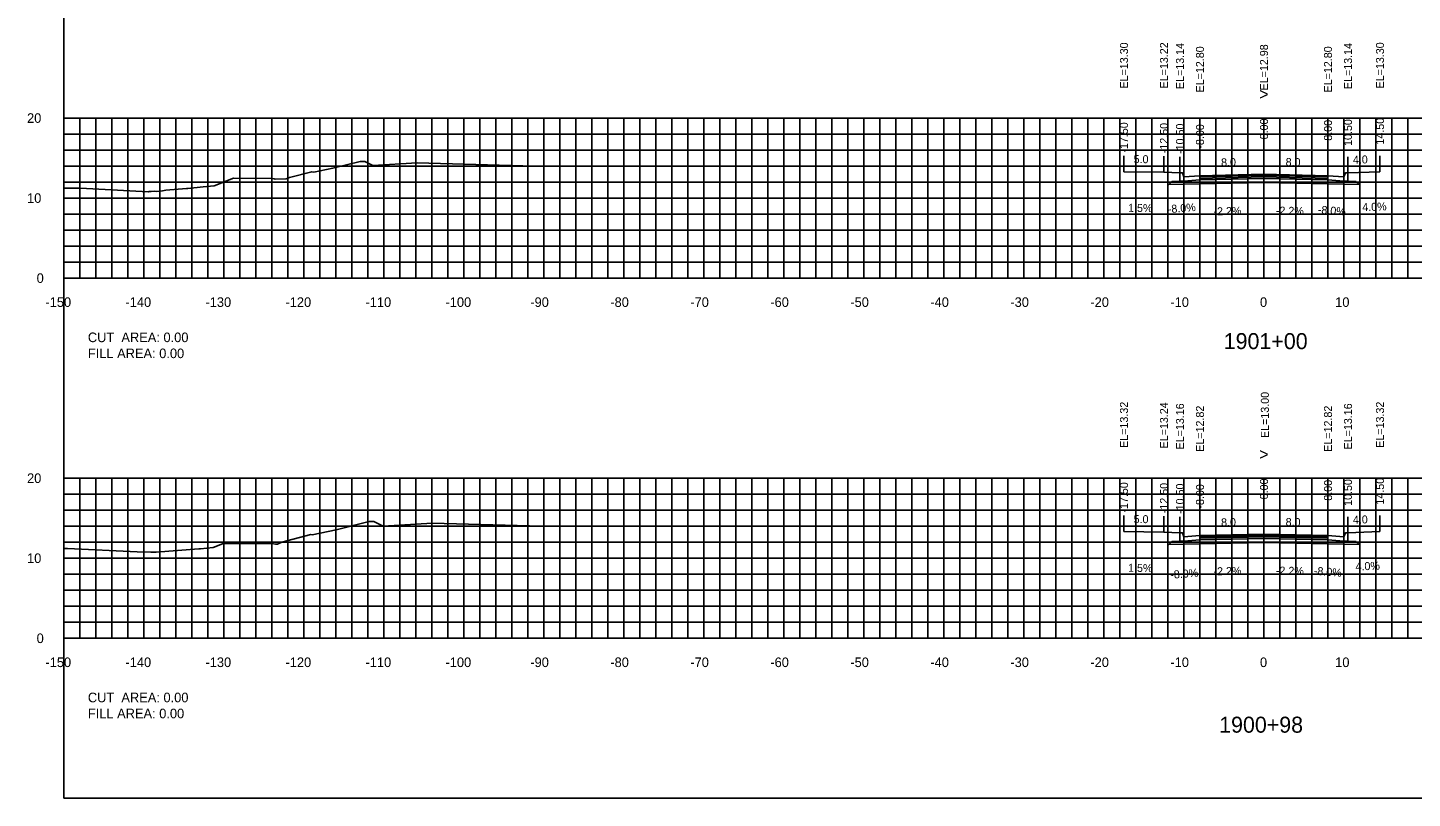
# Model space of a CAD drawing. Extents: x 1800768 to 1802445, y 250079 to 250269.
# Drawn here: x 1802136.5 to 1802309.5, y 250079.4 to 250175.7 of the extents above; entities that cross this region are included whole.
import ezdxf

# ---------------------------------------------------------------- set-up
doc = ezdxf.new("R2010")
doc.units = 0
for name, color, linetype in [('1', 7, 'Continuous'), ('10', 7, 'Continuous'), ('3', 7, 'Continuous'), ('31', 7, 'Continuous'), ('4', 7, 'Continuous'), ('60', 7, 'Continuous'), ('ANNO-TXT', 7, 'Continuous'), ('BASE', 7, 'Continuous'), ('CL-CNST', 7, 'Continuous'), ('Level 62', 7, 'Continuous'), ('LOWER BINDER', 7, 'Continuous'), ('M-ROADS', 7, 'Continuous'), ('UPPER BINDER', 7, 'Continuous'), ('WEARING', 7, 'Continuous')]:
    doc.layers.add(name, color=color, linetype=linetype)

msp = doc.modelspace()

# ---------------------------------------------------------------- linework, layer by layer
for p, q in [((1802273.5, 250157.73), (1802273.5, 250159.73)), ((1802278.5, 250157.66), (1802278.5, 250159.66)), ((1802280.5, 250157.57), (1802280.5, 250159.57)), ((1802291, 250157.41), (1802291, 250159.41)), ((1802301.5, 250157.57), (1802301.5, 250159.57)), ((1802305.5, 250157.73), (1802305.5, 250159.73)), ((1802283, 250157.23), (1802283, 250159.23)), ((1802299, 250157.23), (1802299, 250159.23)), ((1802273.5, 250112.75), (1802273.5, 250114.75)), ((1802278.5, 250112.68), (1802278.5, 250114.68)), ((1802280.5, 250112.6), (1802280.5, 250114.6)), ((1802291, 250112.43), (1802291, 250114.43)), ((1802301.5, 250112.6), (1802301.5, 250114.6)), ((1802305.5, 250112.76), (1802305.5, 250114.76)), ((1802283, 250112.26), (1802283, 250114.26)), ((1802299, 250112.26), (1802299, 250114.26))]:
    msp.add_line(p, q)
for points in [[(1802141, 250079.43), (1802441, 250079.43), (1802441, 250269.43), (1802141, 250269.43)], [(1802283, 250157.23), (1802281, 250157.07), (1802280.83, 250157.57), (1802280.5, 250157.57), (1802280.5, 250156.54), (1802281, 250156.54), (1802283, 250156.7)], [(1802299, 250157.23), (1802301, 250157.07), (1802301.17, 250157.57), (1802301.5, 250157.57), (1802301.5, 250156.54), (1802301, 250156.54), (1802299, 250156.7)], [(1802283, 250112.26), (1802281, 250112.1), (1802280.83, 250112.6), (1802280.5, 250112.6), (1802280.5, 250111.57), (1802281, 250111.57), (1802283, 250111.73)], [(1802299, 250112.26), (1802301, 250112.1), (1802301.17, 250112.6), (1802301.5, 250112.6), (1802301.5, 250111.57), (1802301, 250111.57), (1802299, 250111.73)]]:
    msp.add_lwpolyline(points, close=True)
at = {"layer": '60'}
for p, q in [((1802140.94, 250164.43), (1802141, 250164.43)), ((1802141, 250144.43), (1802141, 250164.43)), ((1802140.94, 250154.43), (1802141, 250154.43)), ((1802140.94, 250144.43), (1802141, 250144.43)), ((1802141, 250144.43), (1802441, 250144.43)), ((1802141, 250144.37), (1802141, 250144.43)), ((1802151, 250144.37), (1802151, 250144.43)), ((1802161, 250144.37), (1802161, 250144.43)), ((1802171, 250144.37), (1802171, 250144.43)), ((1802181, 250144.37), (1802181, 250144.43)), ((1802191, 250144.37), (1802191, 250144.43)), ((1802201, 250144.37), (1802201, 250144.43)), ((1802211, 250144.37), (1802211, 250144.43)), ((1802221, 250144.37), (1802221, 250144.43)), ((1802231, 250144.37), (1802231, 250144.43)), ((1802241, 250144.37), (1802241, 250144.43)), ((1802251, 250144.37), (1802251, 250144.43)), ((1802261, 250144.37), (1802261, 250144.43)), ((1802271, 250144.37), (1802271, 250144.43)), ((1802281, 250144.37), (1802281, 250144.43)), ((1802291, 250144.37), (1802291, 250144.43)), ((1802301, 250144.37), (1802301, 250144.43)), ((1802140.94, 250119.43), (1802141, 250119.43)), ((1802141, 250099.43), (1802141, 250119.43)), ((1802140.94, 250109.43), (1802141, 250109.43)), ((1802140.94, 250099.43), (1802141, 250099.43)), ((1802141, 250099.43), (1802441, 250099.43)), ((1802141, 250099.37), (1802141, 250099.43)), ((1802151, 250099.37), (1802151, 250099.43)), ((1802161, 250099.37), (1802161, 250099.43)), ((1802171, 250099.37), (1802171, 250099.43)), ((1802181, 250099.37), (1802181, 250099.43)), ((1802191, 250099.37), (1802191, 250099.43)), ((1802201, 250099.37), (1802201, 250099.43)), ((1802211, 250099.37), (1802211, 250099.43)), ((1802221, 250099.37), (1802221, 250099.43)), ((1802231, 250099.37), (1802231, 250099.43)), ((1802241, 250099.37), (1802241, 250099.43)), ((1802251, 250099.37), (1802251, 250099.43)), ((1802261, 250099.37), (1802261, 250099.43)), ((1802271, 250099.37), (1802271, 250099.43)), ((1802281, 250099.37), (1802281, 250099.43)), ((1802291, 250099.37), (1802291, 250099.43)), ((1802301, 250099.37), (1802301, 250099.43))]:
    msp.add_line(p, q, dxfattribs=at)
at = {"layer": 'BASE'}
for points in [[(1802299, 250156.2), (1802302.9, 250156.12), (1802302.5, 250156.52), (1802301.5, 250156.54), (1802301, 250156.54), (1802299, 250156.7), (1802291, 250156.88), (1802283, 250156.7), (1802281, 250156.54), (1802280.5, 250156.54), (1802279.5, 250156.52), (1802279.1, 250156.12), (1802283, 250156.2), (1802291, 250156.38)], [(1802299, 250111.23), (1802302.9, 250111.14), (1802302.5, 250111.54), (1802301.5, 250111.57), (1802301, 250111.57), (1802299, 250111.73), (1802291, 250111.9), (1802283, 250111.73), (1802281, 250111.57), (1802280.5, 250111.57), (1802279.5, 250111.54), (1802279.1, 250111.14), (1802283, 250111.23), (1802291, 250111.4)]]:
    msp.add_lwpolyline(points, close=True, dxfattribs=at)
at = {"layer": 'CL-CNST'}
for points in [[(1802273.5, 250157.73), (1802278.5, 250157.66), (1802280.5, 250157.57), (1802280.83, 250157.57), (1802281, 250157.07), (1802283, 250157.23), (1802291, 250157.41), (1802299, 250157.23), (1802301, 250157.07), (1802301.17, 250157.57), (1802301.5, 250157.57), (1802305.5, 250157.73)], [(1802273.5, 250112.75), (1802278.5, 250112.68), (1802280.5, 250112.6), (1802280.83, 250112.6), (1802281, 250112.1), (1802283, 250112.26), (1802291, 250112.43), (1802299, 250112.26), (1802301, 250112.1), (1802301.17, 250112.6), (1802301.5, 250112.6), (1802305.5, 250112.76)]]:
    msp.add_lwpolyline(points, dxfattribs=at)
at = {"layer": 'Level 62'}
for p, q in [((1802141, 250164.43), (1802441, 250164.43)), ((1802141, 250144.43), (1802141, 250164.43)), ((1802143, 250144.43), (1802143, 250164.43)), ((1802145, 250144.43), (1802145, 250164.43)), ((1802147, 250144.43), (1802147, 250164.43)), ((1802149, 250144.43), (1802149, 250164.43)), ((1802151, 250144.43), (1802151, 250164.43)), ((1802153, 250144.43), (1802153, 250164.43)), ((1802155, 250144.43), (1802155, 250164.43)), ((1802157, 250144.43), (1802157, 250164.43)), ((1802159, 250144.43), (1802159, 250164.43)), ((1802161, 250144.43), (1802161, 250164.43)), ((1802163, 250144.43), (1802163, 250164.43)), ((1802165, 250144.43), (1802165, 250164.43)), ((1802167, 250144.43), (1802167, 250164.43)), ((1802169, 250144.43), (1802169, 250164.43)), ((1802171, 250144.43), (1802171, 250164.43)), ((1802173, 250144.43), (1802173, 250164.43)), ((1802175, 250144.43), (1802175, 250164.43)), ((1802177, 250144.43), (1802177, 250164.43)), ((1802179, 250144.43), (1802179, 250164.43)), ((1802181, 250144.43), (1802181, 250164.43)), ((1802183, 250144.43), (1802183, 250164.43)), ((1802185, 250144.43), (1802185, 250164.43)), ((1802187, 250144.43), (1802187, 250164.43)), ((1802189, 250144.43), (1802189, 250164.43)), ((1802191, 250144.43), (1802191, 250164.43)), ((1802193, 250144.43), (1802193, 250164.43)), ((1802195, 250144.43), (1802195, 250164.43)), ((1802197, 250144.43), (1802197, 250164.43)), ((1802199, 250144.43), (1802199, 250164.43)), ((1802201, 250144.43), (1802201, 250164.43)), ((1802203, 250144.43), (1802203, 250164.43)), ((1802205, 250144.43), (1802205, 250164.43)), ((1802207, 250144.43), (1802207, 250164.43)), ((1802209, 250144.43), (1802209, 250164.43)), ((1802211, 250144.43), (1802211, 250164.43)), ((1802213, 250144.43), (1802213, 250164.43)), ((1802215, 250144.43), (1802215, 250164.43)), ((1802217, 250144.43), (1802217, 250164.43)), ((1802219, 250144.43), (1802219, 250164.43)), ((1802221, 250144.43), (1802221, 250164.43)), ((1802223, 250144.43), (1802223, 250164.43)), ((1802225, 250144.43), (1802225, 250164.43)), ((1802227, 250144.43), (1802227, 250164.43)), ((1802229, 250144.43), (1802229, 250164.43)), ((1802231, 250144.43), (1802231, 250164.43)), ((1802233, 250144.43), (1802233, 250164.43)), ((1802235, 250144.43), (1802235, 250164.43)), ((1802237, 250144.43), (1802237, 250164.43)), ((1802239, 250144.43), (1802239, 250164.43)), ((1802241, 250144.43), (1802241, 250164.43)), ((1802243, 250144.43), (1802243, 250164.43)), ((1802245, 250144.43), (1802245, 250164.43)), ((1802247, 250144.43), (1802247, 250164.43)), ((1802249, 250144.43), (1802249, 250164.43)), ((1802251, 250144.43), (1802251, 250164.43)), ((1802253, 250144.43), (1802253, 250164.43)), ((1802255, 250144.43), (1802255, 250164.43)), ((1802257, 250144.43), (1802257, 250164.43)), ((1802259, 250144.43), (1802259, 250164.43)), ((1802261, 250144.43), (1802261, 250164.43)), ((1802263, 250144.43), (1802263, 250164.43)), ((1802265, 250144.43), (1802265, 250164.43)), ((1802267, 250144.43), (1802267, 250164.43)), ((1802269, 250144.43), (1802269, 250164.43)), ((1802271, 250144.43), (1802271, 250164.43)), ((1802273, 250144.43), (1802273, 250164.43)), ((1802275, 250144.43), (1802275, 250164.43)), ((1802277, 250144.43), (1802277, 250164.43)), ((1802279, 250144.43), (1802279, 250164.43)), ((1802281, 250144.43), (1802281, 250164.43)), ((1802283, 250144.43), (1802283, 250164.43)), ((1802285, 250144.43), (1802285, 250164.43)), ((1802287, 250144.43), (1802287, 250164.43)), ((1802289, 250144.43), (1802289, 250164.43)), ((1802291, 250144.43), (1802291, 250164.43)), ((1802293, 250144.43), (1802293, 250164.43)), ((1802295, 250144.43), (1802295, 250164.43)), ((1802297, 250144.43), (1802297, 250164.43)), ((1802299, 250144.43), (1802299, 250164.43)), ((1802301, 250144.43), (1802301, 250164.43)), ((1802303, 250144.43), (1802303, 250164.43)), ((1802305, 250144.43), (1802305, 250164.43)), ((1802307, 250144.43), (1802307, 250164.43)), ((1802309, 250144.43), (1802309, 250164.43)), ((1802141, 250162.43), (1802441, 250162.43)), ((1802141, 250160.43), (1802441, 250160.43)), ((1802141, 250158.43), (1802441, 250158.43)), ((1802141, 250156.43), (1802441, 250156.43)), ((1802141, 250154.43), (1802441, 250154.43)), ((1802141, 250152.43), (1802441, 250152.43)), ((1802141, 250150.43), (1802441, 250150.43)), ((1802141, 250148.43), (1802441, 250148.43)), ((1802141, 250146.43), (1802441, 250146.43)), ((1802141, 250144.43), (1802441, 250144.43)), ((1802141, 250119.43), (1802441, 250119.43)), ((1802141, 250099.43), (1802141, 250119.43)), ((1802143, 250099.43), (1802143, 250119.43)), ((1802145, 250099.43), (1802145, 250119.43)), ((1802147, 250099.43), (1802147, 250119.43)), ((1802149, 250099.43), (1802149, 250119.43)), ((1802151, 250099.43), (1802151, 250119.43)), ((1802153, 250099.43), (1802153, 250119.43)), ((1802155, 250099.43), (1802155, 250119.43)), ((1802157, 250099.43), (1802157, 250119.43)), ((1802159, 250099.43), (1802159, 250119.43)), ((1802161, 250099.43), (1802161, 250119.43)), ((1802163, 250099.43), (1802163, 250119.43)), ((1802165, 250099.43), (1802165, 250119.43)), ((1802167, 250099.43), (1802167, 250119.43)), ((1802169, 250099.43), (1802169, 250119.43)), ((1802171, 250099.43), (1802171, 250119.43)), ((1802173, 250099.43), (1802173, 250119.43)), ((1802175, 250099.43), (1802175, 250119.43)), ((1802177, 250099.43), (1802177, 250119.43)), ((1802179, 250099.43), (1802179, 250119.43)), ((1802181, 250099.43), (1802181, 250119.43)), ((1802183, 250099.43), (1802183, 250119.43)), ((1802185, 250099.43), (1802185, 250119.43)), ((1802187, 250099.43), (1802187, 250119.43)), ((1802189, 250099.43), (1802189, 250119.43)), ((1802191, 250099.43), (1802191, 250119.43)), ((1802193, 250099.43), (1802193, 250119.43)), ((1802195, 250099.43), (1802195, 250119.43)), ((1802197, 250099.43), (1802197, 250119.43)), ((1802199, 250099.43), (1802199, 250119.43)), ((1802201, 250099.43), (1802201, 250119.43)), ((1802203, 250099.43), (1802203, 250119.43)), ((1802205, 250099.43), (1802205, 250119.43)), ((1802207, 250099.43), (1802207, 250119.43)), ((1802209, 250099.43), (1802209, 250119.43)), ((1802211, 250099.43), (1802211, 250119.43)), ((1802213, 250099.43), (1802213, 250119.43)), ((1802215, 250099.43), (1802215, 250119.43)), ((1802217, 250099.43), (1802217, 250119.43)), ((1802219, 250099.43), (1802219, 250119.43)), ((1802221, 250099.43), (1802221, 250119.43)), ((1802223, 250099.43), (1802223, 250119.43)), ((1802225, 250099.43), (1802225, 250119.43)), ((1802227, 250099.43), (1802227, 250119.43)), ((1802229, 250099.43), (1802229, 250119.43)), ((1802231, 250099.43), (1802231, 250119.43)), ((1802233, 250099.43), (1802233, 250119.43)), ((1802235, 250099.43), (1802235, 250119.43)), ((1802237, 250099.43), (1802237, 250119.43)), ((1802239, 250099.43), (1802239, 250119.43)), ((1802241, 250099.43), (1802241, 250119.43)), ((1802243, 250099.43), (1802243, 250119.43)), ((1802245, 250099.43), (1802245, 250119.43)), ((1802247, 250099.43), (1802247, 250119.43)), ((1802249, 250099.43), (1802249, 250119.43)), ((1802251, 250099.43), (1802251, 250119.43)), ((1802253, 250099.43), (1802253, 250119.43)), ((1802255, 250099.43), (1802255, 250119.43)), ((1802257, 250099.43), (1802257, 250119.43)), ((1802259, 250099.43), (1802259, 250119.43)), ((1802261, 250099.43), (1802261, 250119.43)), ((1802263, 250099.43), (1802263, 250119.43)), ((1802265, 250099.43), (1802265, 250119.43)), ((1802267, 250099.43), (1802267, 250119.43)), ((1802269, 250099.43), (1802269, 250119.43)), ((1802271, 250099.43), (1802271, 250119.43)), ((1802273, 250099.43), (1802273, 250119.43)), ((1802275, 250099.43), (1802275, 250119.43)), ((1802277, 250099.43), (1802277, 250119.43)), ((1802279, 250099.43), (1802279, 250119.43)), ((1802281, 250099.43), (1802281, 250119.43)), ((1802283, 250099.43), (1802283, 250119.43)), ((1802285, 250099.43), (1802285, 250119.43)), ((1802287, 250099.43), (1802287, 250119.43)), ((1802289, 250099.43), (1802289, 250119.43)), ((1802291, 250099.43), (1802291, 250119.43)), ((1802293, 250099.43), (1802293, 250119.43)), ((1802295, 250099.43), (1802295, 250119.43)), ((1802297, 250099.43), (1802297, 250119.43)), ((1802299, 250099.43), (1802299, 250119.43)), ((1802301, 250099.43), (1802301, 250119.43)), ((1802303, 250099.43), (1802303, 250119.43)), ((1802305, 250099.43), (1802305, 250119.43)), ((1802307, 250099.43), (1802307, 250119.43)), ((1802309, 250099.43), (1802309, 250119.43)), ((1802141, 250117.43), (1802441, 250117.43)), ((1802141, 250115.43), (1802441, 250115.43)), ((1802141, 250113.43), (1802441, 250113.43)), ((1802141, 250111.43), (1802441, 250111.43)), ((1802141, 250109.43), (1802441, 250109.43)), ((1802141, 250107.43), (1802441, 250107.43)), ((1802141, 250105.43), (1802441, 250105.43)), ((1802141, 250103.43), (1802441, 250103.43)), ((1802141, 250101.43), (1802441, 250101.43)), ((1802141, 250099.43), (1802441, 250099.43))]:
    msp.add_line(p, q, dxfattribs=at)
at = {"layer": 'LOWER BINDER'}
for points in [[(1802283, 250156.7), (1802283, 250156.89), (1802291, 250157.07), (1802299, 250156.89), (1802299, 250156.7), (1802291, 250156.88)], [(1802283, 250111.73), (1802283, 250111.92), (1802291, 250112.09), (1802299, 250111.92), (1802299, 250111.73), (1802291, 250111.9)]]:
    msp.add_lwpolyline(points, close=True, dxfattribs=at)
at = {"layer": 'M-ROADS'}
for points in [[(1802141, 250155.66), (1802141.8, 250155.65), (1802143.09, 250155.65), (1802151.53, 250155.23), (1802151.68, 250155.24), (1802151.91, 250155.26), (1802152.31, 250155.29), (1802152.62, 250155.27), (1802153.33, 250155.34), (1802153.73, 250155.4), (1802156.33, 250155.63), (1802156.48, 250155.64), (1802158.41, 250155.82), (1802159.8, 250155.95), (1802162.22, 250156.91), (1802166.92, 250156.89), (1802167.28, 250156.82), (1802167.4, 250156.8), (1802168.79, 250156.84), (1802169.21, 250157.02), (1802171.99, 250157.73), (1802172.23, 250157.69), (1802174.63, 250158.19), (1802178.03, 250159), (1802178.45, 250159), (1802178.62, 250159), (1802179.61, 250158.51), (1802185.14, 250158.82), (1802199.81, 250158.43)], [(1802141, 250110.64), (1802141.46, 250110.64), (1802150.15, 250110.22), (1802151.86, 250110.2), (1802152.1, 250110.18), (1802152.11, 250110.18), (1802152.53, 250110.19), (1802157.87, 250110.61), (1802157.88, 250110.61), (1802158.1, 250110.61), (1802159.67, 250110.76), (1802160.83, 250111.23), (1802167, 250111.28), (1802167.46, 250111.19), (1802167.48, 250111.19), (1802167.7, 250111.2), (1802168.25, 250111.43), (1802171.87, 250112.38), (1802172.05, 250112.36), (1802175.05, 250112.99), (1802179.14, 250114), (1802179.63, 250114), (1802179.75, 250114), (1802180.9, 250113.42), (1802187.05, 250113.8), (1802200.71, 250113.42)]]:
    msp.add_lwpolyline(points, dxfattribs=at)
at = {"layer": 'UPPER BINDER'}
for points in [[(1802283, 250157.08), (1802291, 250157.26), (1802299, 250157.08), (1802299, 250156.89), (1802291, 250157.07), (1802283, 250156.89)], [(1802283, 250112.11), (1802291, 250112.28), (1802299, 250112.11), (1802299, 250111.92), (1802291, 250112.09), (1802283, 250111.92)]]:
    msp.add_lwpolyline(points, close=True, dxfattribs=at)
at = {"layer": 'WEARING'}
for points in [[(1802299, 250157.08), (1802299, 250157.23), (1802291, 250157.41), (1802283, 250157.23), (1802283, 250157.08), (1802291, 250157.26)], [(1802299, 250112.11), (1802299, 250112.26), (1802291, 250112.43), (1802283, 250112.26), (1802283, 250112.11), (1802291, 250112.28)]]:
    msp.add_lwpolyline(points, close=True, dxfattribs=at)

# ---------------------------------------------------------------- texts
at = {"layer": '1'}
for s, p in [('1901+00', (1802285.97, 250135.56)), ('1900+98', (1802285.4, 250087.63))]:
    msp.add_text(s, height=2, dxfattribs=at).set_placement(p)
at = {"layer": '10'}
for s, p in [('-150', (1802138.7, 250140.83)), ('-140', (1802148.7, 250140.83)), ('-130', (1802158.7, 250140.83)), ('-120', (1802168.7, 250140.83)), ('-110', (1802178.7, 250140.83)), ('-100', (1802188.7, 250140.83)), ('-90', (1802199.3, 250140.83)), ('-80', (1802209.3, 250140.83)), ('-70', (1802219.3, 250140.83)), ('-60', (1802229.3, 250140.83)), ('-50', (1802239.3, 250140.83)), ('-40', (1802249.3, 250140.83)), ('-30', (1802259.3, 250140.83)), ('-20', (1802269.3, 250140.83)), ('-10', (1802279.3, 250140.83)), ('0', (1802290.5, 250140.83)), ('10', (1802299.9, 250140.83)), ('-150', (1802138.7, 250095.83)), ('-140', (1802148.7, 250095.83)), ('-130', (1802158.7, 250095.83)), ('-120', (1802168.7, 250095.83)), ('-110', (1802178.7, 250095.83)), ('-100', (1802188.7, 250095.83)), ('-90', (1802199.3, 250095.83)), ('-80', (1802209.3, 250095.83)), ('-70', (1802219.3, 250095.83)), ('-60', (1802229.3, 250095.83)), ('-50', (1802239.3, 250095.83)), ('-40', (1802249.3, 250095.83)), ('-30', (1802259.3, 250095.83)), ('-20', (1802269.3, 250095.83)), ('-10', (1802279.3, 250095.83)), ('0', (1802290.5, 250095.83)), ('10', (1802299.9, 250095.83))]:
    msp.add_text(s, height=1.2, dxfattribs=at).set_placement(p)
at = {"layer": '3'}
for s, p in [('EL=13.30', (1802274, 250168.12)), ('EL=13.22', (1802279, 250168.13)), ('EL=13.14', (1802281, 250168.05)), ('EL=12.80', (1802283.5, 250167.63)), ('EL=12.98', (1802291.5, 250167.88)), ('EL=12.80', (1802299.5, 250167.63)), ('EL=13.14', (1802302, 250168.05)), ('EL=13.30', (1802306, 250168.13)), ('-17.50', (1802274, 250160.11)), ('-12.50', (1802279, 250160.03)), ('-10.50', (1802281, 250159.95)), ('-8.00', (1802283.5, 250160.61)), ('0.00', (1802291.5, 250161.77)), ('8.00', (1802299.5, 250161.6)), ('10.50', (1802302, 250160.95)), ('14.50', (1802306, 250161.11)), ('EL=13.00', (1802291.61, 250124.45)), ('EL=13.32', (1802274, 250123.22)), ('EL=13.24', (1802279, 250123.15)), ('EL=13.16', (1802281, 250123.02)), ('EL=12.82', (1802283.5, 250122.73)), ('EL=12.82', (1802299.5, 250122.73)), ('EL=13.16', (1802302, 250123.02)), ('EL=13.32', (1802306, 250123.23)), ('-17.50', (1802274, 250115.13)), ('-12.50', (1802279, 250115.05)), ('-10.50', (1802281, 250114.97)), ('-8.00', (1802283.5, 250115.63)), ('0.00', (1802291.5, 250116.79)), ('8.00', (1802299.5, 250116.62)), ('10.50', (1802302, 250115.97)), ('14.50', (1802306, 250116.13))]:
    msp.add_text(s, height=1, rotation=90, dxfattribs=at).set_placement(p)
at = {"layer": '31'}
for s, p in [('20', (1802136.4, 250163.83)), ('10', (1802136.4, 250153.83)), ('0', (1802137.6, 250143.83)), ('20', (1802136.4, 250118.83)), ('10', (1802136.4, 250108.83)), ('0', (1802137.6, 250098.83))]:
    msp.add_text(s, height=1.2, dxfattribs=at).set_placement(p)
at = {"layer": '4'}
for s, rotation, p in [('5.0', 359.1406, (1802274.7, 250158.81)), ('8.0', 1.2603, (1802285.65, 250158.39)), ('8.0', 358.7397, (1802293.7, 250158.45)), ('4.0', 2.2906, (1802302.13, 250158.7)), ('1.5%', 359.1406, (1802274.01, 250152.72)), ('-8.0%', 4.5739, (1802279.02, 250152.54)), ('-2.2%', 1.2603, (1802284.7, 250152.27)), ('-2.2%', 358.7397, (1802292.48, 250152.38)), ('-8.0%', 355.4261, (1802297.7, 250152.51)), ('4.0%', 2.2906, (1802303.3, 250152.78)), ('5.0', 359.1406, (1802274.7, 250113.83)), ('8.0', 1.2603, (1802285.65, 250113.41)), ('8.0', 358.7397, (1802293.7, 250113.47)), ('4.0', 2.2906, (1802302.13, 250113.72)), ('1.5%', 359.1406, (1802274.01, 250107.74)), ('-8.0%', 4.5739, (1802279.33, 250106.86)), ('-2.2%', 1.2603, (1802284.7, 250107.29)), ('-2.2%', 358.7397, (1802292.48, 250107.4)), ('-8.0%', 355.4261, (1802297.2, 250107.38)), ('4.0%', 2.2906, (1802302.46, 250107.89))]:
    msp.add_text(s, height=1, rotation=rotation, dxfattribs=at).set_placement(p)
at = {"layer": '60'}
for s, height, p in [('>', 1.5, (1802290.39, 250166.68)), ('-', 0.0001, (1802141, 250144.43)), ('>', 1.5, (1802290.39, 250121.68)), ('-', 0.0001, (1802141, 250099.43))]:
    msp.add_text(s, height=height, dxfattribs=at).set_placement(p)
at = {"layer": 'ANNO-TXT'}
for s, p in [('CUT  AREA: 0.00', (1802144, 250136.43)), ('FILL AREA: 0.00', (1802144, 250134.43)), ('CUT  AREA: 0.00', (1802144, 250091.43)), ('FILL AREA: 0.00', (1802144, 250089.43))]:
    msp.add_text(s, height=1.2, dxfattribs=at).set_placement(p)

doc.saveas('drawing.dxf')
